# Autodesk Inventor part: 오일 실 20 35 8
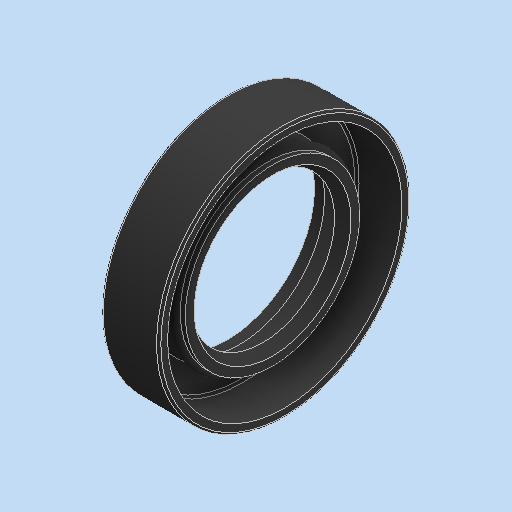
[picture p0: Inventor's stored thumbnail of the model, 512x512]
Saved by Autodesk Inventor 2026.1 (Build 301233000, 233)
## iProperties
Created: 2025-09
Part Number: 오일 실 20 35 8
Material: 고무
Description: 오일-실
Document SubType Name: Modeling
Designer: PC-30
Density: 0.93 g/cm^3
Appearance: 기본값
Author: jhkim
Sending System: Autodesk Inventor 2026
Preprocessor: ST-DEVELOPER v20.1
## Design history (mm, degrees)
feature "Solid1"
node "솔리드1"
